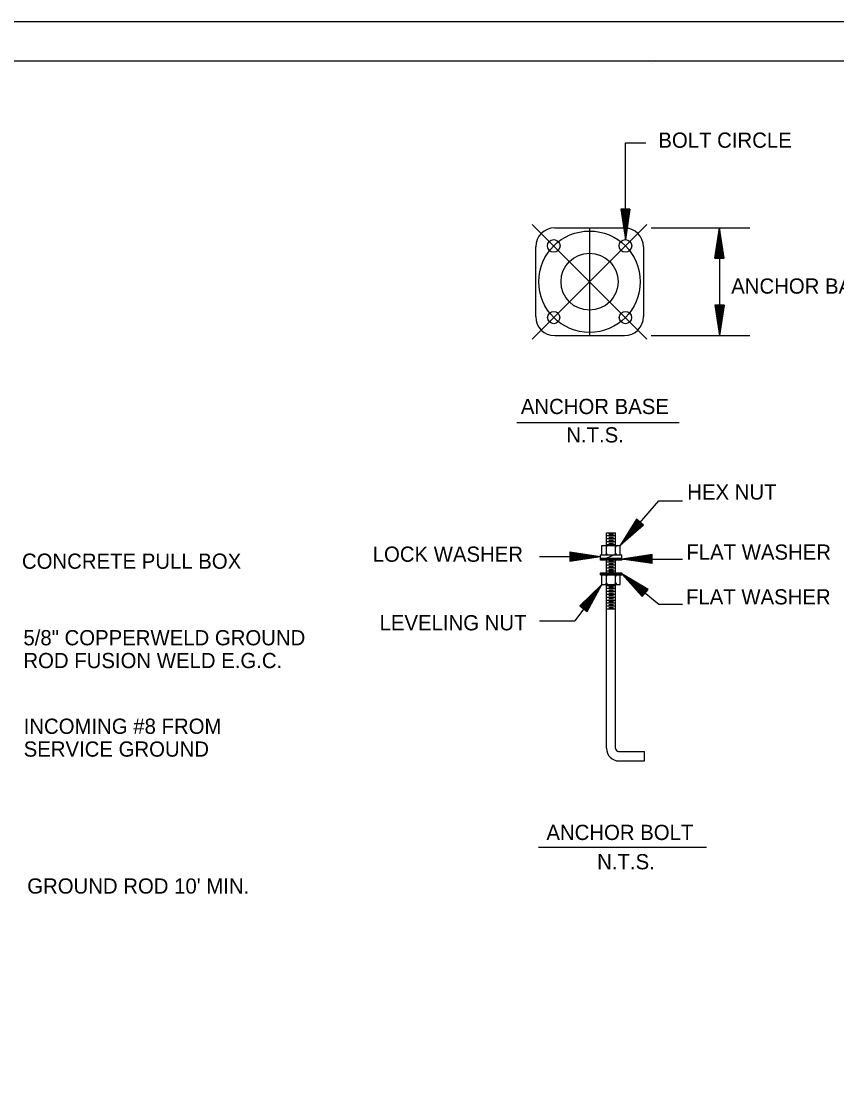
# Model space of a CAD drawing. Extents: x 1370050 to 1370716, y 380076 to 380502.
# Drawn here: x 1370255.2 to 1370415.9, y 380290.6 to 380502.4 of the extents above; entities that cross this region are included whole.
import ezdxf

# ---------------------------------------------------------------- set-up
doc = ezdxf.new("R2010")
doc.units = 0
for name, color, linetype in [('R_Border', 7, 'Continuous'), ('R_Grid', 7, 'Continuous'), ('R_No Plot', 7, 'Continuous')]:
    doc.layers.add(name, color=color, linetype=linetype)

msp = doc.modelspace()

# ---------------------------------------------------------------- linework, layer by layer
at = {"layer": 'R_Border'}
for p, q in [((1370074.49, 380494.58), (1370706.85, 380494.58)), ((1370379.53, 380494.06), (1370379.53, 380494.06)), ((1370379.53, 380494.06), (1370379.53, 380494.06))]:
    msp.add_line(p, q, dxfattribs=at)
at = {"layer": 'R_Grid'}
for p, q in [((1370374.28, 380459.38), (1370374.28, 380478.44)), ((1370374.28, 380478.44), (1370378.31, 380478.44)), ((1370373.38, 380465.38), (1370374.28, 380459.38)), ((1370375.18, 380465.38), (1370373.38, 380465.38)), ((1370373.53, 380465.38), (1370374.28, 380460.38)), ((1370373.68, 380465.38), (1370374.28, 380461.41)), ((1370373.83, 380465.38), (1370374.28, 380462.41)), ((1370373.99, 380465.38), (1370374.28, 380463.43)), ((1370374.14, 380465.38), (1370374.28, 380464.43)), ((1370375.18, 380465.38), (1370374.28, 380459.38)), ((1370374.57, 380465.38), (1370374.28, 380463.43)), ((1370374.88, 380465.38), (1370374.28, 380461.41)), ((1370375.03, 380465.38), (1370374.28, 380460.38)), ((1370374.73, 380465.38), (1370374.28, 380462.41)), ((1370374.42, 380465.38), (1370374.28, 380464.43)), ((1370378.52, 380439.74), (1370355.9, 380462.37)), ((1370355.9, 380439.74), (1370378.52, 380462.37)), ((1370360.34, 380461.68), (1370374.09, 380461.68)), ((1370367.21, 380461.68), (1370367.21, 380440.43)), ((1370379.34, 380461.68), (1370398.84, 380461.68)), ((1370391.94, 380455.68), (1370392.84, 380461.68)), ((1370392.84, 380461.68), (1370392.84, 380440.43)), ((1370393.74, 380455.68), (1370392.84, 380461.68)), ((1370392.09, 380455.68), (1370392.84, 380460.68)), ((1370392.24, 380455.68), (1370392.84, 380459.65)), ((1370393.59, 380455.68), (1370392.84, 380460.68)), ((1370393.43, 380455.68), (1370392.84, 380459.65)), ((1370356.59, 380444.18), (1370356.59, 380457.93)), ((1370377.84, 380457.93), (1370377.84, 380444.18)), ((1370392.39, 380455.68), (1370392.84, 380458.65)), ((1370392.54, 380455.68), (1370392.84, 380457.63)), ((1370392.69, 380455.68), (1370392.84, 380456.63)), ((1370393.28, 380455.68), (1370392.84, 380458.65)), ((1370393.13, 380455.68), (1370392.84, 380457.63)), ((1370392.98, 380455.68), (1370392.84, 380456.63)), ((1370391.94, 380455.68), (1370393.74, 380455.68)), ((1370391.94, 380446.43), (1370392.84, 380440.43)), ((1370393.74, 380446.43), (1370391.94, 380446.43)), ((1370392.09, 380446.43), (1370392.84, 380441.43)), ((1370392.24, 380446.43), (1370392.84, 380442.47)), ((1370392.39, 380446.43), (1370392.84, 380443.47)), ((1370392.54, 380446.43), (1370392.84, 380444.48)), ((1370392.69, 380446.43), (1370392.84, 380445.48)), ((1370393.74, 380446.43), (1370392.84, 380440.43)), ((1370393.13, 380446.43), (1370392.84, 380444.48)), ((1370393.43, 380446.43), (1370392.84, 380442.47)), ((1370393.59, 380446.43), (1370392.84, 380441.43)), ((1370393.28, 380446.43), (1370392.84, 380443.47)), ((1370392.98, 380446.43), (1370392.84, 380445.48)), ((1370360.34, 380440.43), (1370374.09, 380440.43)), ((1370379.34, 380440.43), (1370398.84, 380440.43)), ((1370384.9, 380423.23), (1370352.84, 380423.23)), ((1370373.25, 380399.08), (1370380.86, 380407.86)), ((1370380.86, 380407.86), (1370385.55, 380407.86)), ((1370376.49, 380404.22), (1370373.25, 380399.08)), ((1370376.6, 380404.12), (1370373.91, 380399.84)), ((1370376.72, 380404.02), (1370374.58, 380400.62)), ((1370376.83, 380403.92), (1370375.23, 380401.38)), ((1370376.95, 380403.82), (1370375.9, 380402.15)), ((1370377.85, 380403.04), (1370376.49, 380404.22)), ((1370377.06, 380403.72), (1370376.55, 380402.91)), ((1370370.55, 380401.58), (1370372.35, 380401.58)), ((1370370.55, 380399.08), (1370370.55, 380401.58)), ((1370372.35, 380399.08), (1370372.35, 380401.58)), ((1370377.85, 380403.04), (1370373.25, 380399.08)), ((1370377.74, 380403.14), (1370373.91, 380399.84)), ((1370377.62, 380403.24), (1370374.58, 380400.62)), ((1370377.51, 380403.34), (1370375.23, 380401.38)), ((1370377.39, 380403.44), (1370375.9, 380402.15)), ((1370377.28, 380403.54), (1370376.55, 380402.91)), ((1370370.55, 380401.01), (1370372.35, 380401.01)), ((1370370.55, 380400.43), (1370372.35, 380400.43)), ((1370370.55, 380399.85), (1370372.35, 380399.85)), ((1370371, 380401.28), (1370371.9, 380401.28)), ((1370371, 380400.71), (1370371.9, 380400.71)), ((1370371, 380400.13), (1370371.9, 380400.13)), ((1370371, 380399.55), (1370371.9, 380399.55)), ((1370363.35, 380397.79), (1370369.35, 380396.89)), ((1370363.35, 380397.79), (1370363.35, 380395.99)), ((1370363.35, 380397.64), (1370368.35, 380396.89)), ((1370363.35, 380397.48), (1370367.32, 380396.89)), ((1370363.35, 380397.33), (1370366.32, 380396.89)), ((1370369.65, 380397.19), (1370369.65, 380399.08)), ((1370369.65, 380399.08), (1370373.25, 380399.08)), ((1370370.55, 380399.28), (1370372.35, 380399.28)), ((1370370.55, 380397.19), (1370370.55, 380399.08)), ((1370372.35, 380397.19), (1370372.35, 380399.08)), ((1370373.25, 380397.19), (1370373.25, 380399.08)), ((1370357.35, 380396.89), (1370369.35, 380396.89)), ((1370363.35, 380397.18), (1370365.3, 380396.89)), ((1370363.35, 380397.03), (1370364.3, 380396.89)), ((1370363.35, 380395.99), (1370369.35, 380396.89)), ((1370363.35, 380396.59), (1370365.3, 380396.89)), ((1370363.35, 380396.29), (1370367.32, 380396.89)), ((1370363.35, 380396.14), (1370368.35, 380396.89)), ((1370363.35, 380396.44), (1370366.32, 380396.89)), ((1370363.35, 380396.75), (1370364.3, 380396.89)), ((1370369.35, 380396.19), (1370369.35, 380397.19)), ((1370369.35, 380397.19), (1370373.55, 380397.19)), ((1370369.35, 380396.59), (1370373.55, 380396.59)), ((1370369.35, 380396.21), (1370369.73, 380396.59)), ((1370369.35, 380396.42), (1370369.52, 380396.59)), ((1370373.55, 380396.19), (1370369.35, 380396.19)), ((1370369.54, 380396.19), (1370369.94, 380396.59)), ((1370369.75, 380396.19), (1370370.15, 380396.59)), ((1370369.97, 380396.19), (1370370.37, 380396.59)), ((1370370.18, 380396.19), (1370370.58, 380396.59)), ((1370370.39, 380396.19), (1370370.79, 380396.59)), ((1370370.55, 380393.69), (1370370.55, 380396.19)), ((1370370.55, 380395.81), (1370372.35, 380395.81)), ((1370370.55, 380395.24), (1370372.35, 380395.24)), ((1370370.56, 380396.59), (1370371.87, 380397.17)), ((1370370.6, 380396.19), (1370371, 380396.59)), ((1370370.82, 380396.19), (1370371.22, 380396.59)), ((1370371, 380396.09), (1370371.9, 380396.09)), ((1370371, 380395.51), (1370371.9, 380395.51)), ((1370371.03, 380396.19), (1370371.43, 380396.59)), ((1370371.24, 380396.19), (1370371.64, 380396.59)), ((1370371.45, 380396.19), (1370371.85, 380396.59)), ((1370371.66, 380396.19), (1370372.06, 380396.59)), ((1370371.88, 380396.19), (1370372.28, 380396.59)), ((1370372.09, 380396.19), (1370372.49, 380396.59)), ((1370372.3, 380396.19), (1370372.7, 380396.59)), ((1370372.35, 380393.69), (1370372.35, 380396.19)), ((1370372.51, 380396.19), (1370372.91, 380396.59)), ((1370372.72, 380396.19), (1370373.12, 380396.59)), ((1370372.94, 380396.19), (1370373.34, 380396.59)), ((1370373.15, 380396.19), (1370373.55, 380396.59)), ((1370373.36, 380396.19), (1370373.55, 380396.38)), ((1370379.55, 380397.29), (1370373.55, 380396.39)), ((1370373.55, 380396.19), (1370373.55, 380397.19)), ((1370373.55, 380396.39), (1370385.55, 380396.39)), ((1370379.55, 380395.49), (1370373.55, 380396.39)), ((1370379.55, 380397.14), (1370374.55, 380396.39)), ((1370379.55, 380395.64), (1370374.55, 380396.39)), ((1370379.55, 380396.98), (1370375.58, 380396.39)), ((1370379.55, 380395.79), (1370375.58, 380396.39)), ((1370379.55, 380396.83), (1370376.58, 380396.39)), ((1370379.55, 380395.94), (1370376.58, 380396.39)), ((1370379.55, 380396.68), (1370377.6, 380396.39)), ((1370379.55, 380396.1), (1370377.6, 380396.39)), ((1370379.55, 380396.53), (1370378.6, 380396.39)), ((1370379.55, 380396.25), (1370378.6, 380396.39)), ((1370379.55, 380395.49), (1370379.55, 380397.29)), ((1370369.35, 380393.29), (1370369.35, 380393.69)), ((1370369.35, 380393.69), (1370373.55, 380393.69)), ((1370369.35, 380393.48), (1370369.55, 380393.69)), ((1370369.35, 380393.29), (1370373.55, 380393.29)), ((1370369.37, 380393.29), (1370369.77, 380393.69)), ((1370369.58, 380393.29), (1370369.98, 380393.69)), ((1370369.65, 380391.39), (1370369.65, 380393.29)), ((1370369.79, 380393.29), (1370370.19, 380393.69)), ((1370370, 380393.29), (1370370.4, 380393.69)), ((1370370.21, 380393.29), (1370370.61, 380393.69)), ((1370370.43, 380393.29), (1370370.83, 380393.69)), ((1370370.55, 380394.66), (1370372.35, 380394.66)), ((1370370.55, 380394.08), (1370372.35, 380394.08)), ((1370370.55, 380391.39), (1370370.55, 380393.29)), ((1370370.64, 380393.29), (1370371.04, 380393.69)), ((1370370.85, 380393.29), (1370371.25, 380393.69)), ((1370371, 380394.94), (1370371.9, 380394.94)), ((1370371, 380394.36), (1370371.9, 380394.36)), ((1370371, 380393.78), (1370371.9, 380393.78)), ((1370371.06, 380393.29), (1370371.46, 380393.69)), ((1370371.28, 380393.29), (1370371.68, 380393.69)), ((1370371.49, 380393.29), (1370371.89, 380393.69)), ((1370371.7, 380393.29), (1370372.1, 380393.69)), ((1370371.91, 380393.29), (1370372.31, 380393.69)), ((1370372.12, 380393.29), (1370372.52, 380393.69)), ((1370372.34, 380393.29), (1370372.74, 380393.69)), ((1370372.35, 380391.39), (1370372.35, 380393.29)), ((1370372.55, 380393.29), (1370372.95, 380393.69)), ((1370372.76, 380393.29), (1370373.16, 380393.69)), ((1370372.97, 380393.29), (1370373.37, 380393.69)), ((1370373.18, 380393.29), (1370373.55, 380393.65)), ((1370373.25, 380391.39), (1370373.25, 380393.29)), ((1370373.4, 380393.29), (1370373.55, 380393.44)), ((1370373.55, 380393.29), (1370373.55, 380393.69)), ((1370373.55, 380393.49), (1370380.86, 380387.47)), ((1370377.61, 380388.98), (1370373.55, 380393.49)), ((1370378.76, 380390.37), (1370373.55, 380393.49)), ((1370369.65, 380391.39), (1370364.29, 380384.19)), ((1370365.3, 380387.16), (1370369.65, 380391.39)), ((1370366.73, 380386.07), (1370369.65, 380391.39)), ((1370369.65, 380391.39), (1370373.25, 380391.39)), ((1370370.55, 380359.08), (1370370.55, 380391.39)), ((1370370.55, 380391.2), (1370372.35, 380391.2)), ((1370372.35, 380359.06), (1370372.35, 380391.39)), ((1370377.71, 380389.1), (1370374.32, 380392.85)), ((1370378.66, 380390.25), (1370374.32, 380392.85)), ((1370378.56, 380390.14), (1370375.12, 380392.19)), ((1370377.81, 380389.21), (1370375.12, 380392.19)), ((1370377.9, 380389.33), (1370375.89, 380391.56)), ((1370378.47, 380390.02), (1370375.89, 380391.56)), ((1370365.42, 380387.07), (1370369.04, 380390.59)), ((1370365.54, 380386.98), (1370368.42, 380389.77)), ((1370365.66, 380386.89), (1370367.81, 380388.98)), ((1370366.37, 380386.35), (1370367.81, 380388.98)), ((1370366.49, 380386.26), (1370368.42, 380389.77)), ((1370366.61, 380386.16), (1370369.04, 380390.59)), ((1370370.55, 380390.62), (1370372.35, 380390.62)), ((1370370.55, 380390.05), (1370372.35, 380390.05)), ((1370370.55, 380389.47), (1370372.35, 380389.47)), ((1370370.55, 380388.89), (1370372.35, 380388.89)), ((1370371, 380390.9), (1370371.9, 380390.9)), ((1370371, 380390.32), (1370371.9, 380390.32)), ((1370371, 380389.75), (1370371.9, 380389.75)), ((1370371, 380389.17), (1370371.9, 380389.17)), ((1370378.37, 380389.9), (1370376.68, 380390.91)), ((1370378, 380389.45), (1370376.68, 380390.91)), ((1370378.27, 380389.78), (1370377.45, 380390.28)), ((1370378.1, 380389.57), (1370377.45, 380390.28)), ((1370377.61, 380388.98), (1370378.76, 380390.37)), ((1370365.3, 380387.16), (1370366.73, 380386.07)), ((1370365.78, 380386.79), (1370367.2, 380388.17)), ((1370365.9, 380386.7), (1370366.59, 380387.37)), ((1370366.13, 380386.53), (1370366.59, 380387.37)), ((1370366.25, 380386.44), (1370367.2, 380388.17)), ((1370370.55, 380388.31), (1370372.35, 380388.31)), ((1370370.55, 380387.74), (1370372.35, 380387.74)), ((1370370.55, 380387.16), (1370372.35, 380387.16)), ((1370371, 380388.59), (1370371.9, 380388.59)), ((1370371, 380388.01), (1370371.9, 380388.01)), ((1370371, 380387.44), (1370371.9, 380387.44)), ((1370371, 380386.86), (1370371.9, 380386.86)), ((1370380.86, 380387.47), (1370385.55, 380387.47)), ((1370370.55, 380386.58), (1370372.35, 380386.58)), ((1370357.35, 380384.19), (1370364.29, 380384.19)), ((1370372.95, 380358.46), (1370378.05, 380358.46)), ((1370378.05, 380356.58), (1370378.05, 380358.46)), ((1370373.05, 380356.58), (1370378.05, 380356.58)), ((1370390.27, 380339.52), (1370357.11, 380339.52))]:
    msp.add_line(p, q, dxfattribs=at)
for centre, radius in [((1370367.21, 380451.06), 10), ((1370360.14, 380458.13), 1.25), ((1370374.28, 380458.13), 1.25), ((1370367.21, 380451.06), 5.62), ((1370360.14, 380443.99), 1.2), ((1370374.28, 380443.99), 1.2)]:
    msp.add_circle(centre, radius, dxfattribs=at)
for centre, radius, start, end in [((1370360.34, 380457.93), 3.75, 90, 180), ((1370374.09, 380457.93), 3.75, 360, 90), ((1370360.34, 380444.18), 3.75, 180, 270), ((1370374.09, 380444.18), 3.75, 270, 0), ((1370370.25, 380398.78), 0.3, 0, 90), ((1370370.25, 380397.49), 0.3, 270, 0), ((1370370.85, 380398.78), 0.3, 90, 180), ((1370370.85, 380397.49), 0.3, 180, 270), ((1370372.05, 380398.78), 0.3, 0, 90), ((1370372.05, 380397.49), 0.3, 270, 0), ((1370372.65, 380398.78), 0.3, 90, 180), ((1370372.65, 380397.49), 0.3, 180, 270), ((1370370.25, 380392.99), 0.3, 0, 90), ((1370370.85, 380392.99), 0.3, 90, 180), ((1370372.05, 380392.99), 0.3, 0, 90), ((1370372.65, 380392.99), 0.3, 90, 180), ((1370370.25, 380391.69), 0.3, 270, 0), ((1370370.85, 380391.69), 0.3, 180, 270), ((1370372.05, 380391.69), 0.3, 270, 0), ((1370372.65, 380391.69), 0.3, 180, 270), ((1370373.05, 380359.08), 2.5, 180, 270), ((1370372.95, 380359.06), 0.6, 180, 270)]:
    msp.add_arc(centre, radius, start, end, dxfattribs=at)
at = {"layer": 'R_No Plot'}
msp.add_line((1370049.68, 380502.37), (1370716.35, 380502.37), dxfattribs=at)
msp.add_lwpolyline([(1370049.67, 380502.37), (1370716.35, 380502.37), (1370716.35, 380075.69), (1370049.67, 380075.69)], close=True, dxfattribs=at)

# ---------------------------------------------------------------- texts
at = {"layer": 'R_Grid'}
for s, p in [('BOLT CIRCLE', (1370380.78, 380477.47)), ('ANCHOR BASE SQUARE', (1370395.15, 380448.71)), ('ANCHOR BASE', (1370353.66, 380424.97)), ('N.T.S.', (1370362.61, 380419.37)), ('HEX NUT', (1370386.48, 380408.11)), ('CONCRETE PULL BOX', (1370255.26, 380394.47)), ('LOCK WASHER', (1370324.44, 380395.85)), ('FLAT WASHER', (1370386.3, 380396.26)), ('FLAT WASHER', (1370386.23, 380387.44)), ('LEVELING NUT', (1370325.79, 380382.33)), ('5/8" COPPERWELD GROUND ', (1370255.55, 380379.38)), ('ROD FUSION WELD E.G.C.', (1370255.55, 380374.88)), ('INCOMING #8 FROM ', (1370255.6, 380361.93)), ('SERVICE GROUND', (1370255.6, 380357.43)), ('ANCHOR BOLT', (1370358.7, 380341)), ('N.T.S.', (1370368.71, 380335.22)), ("GROUND ROD 10' MIN.", (1370256.3, 380330.43))]:
    msp.add_text(s, height=3, dxfattribs=at).set_placement(p)

doc.saveas('drawing.dxf')
